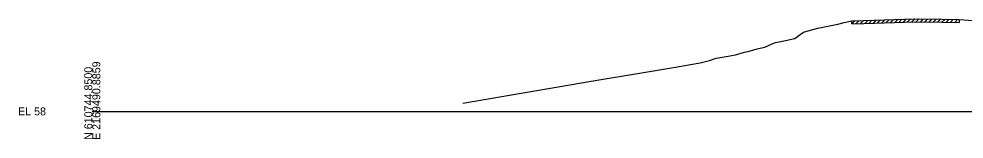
# Model space of a CAD drawing. Extents: x -26 to 6803, y -10 to 19606.
# Drawn here: x 1974.3 to 2305.1, y 8490.3 to 8532.3 of the extents above; entities that cross this region are included whole.
import ezdxf

# ---------------------------------------------------------------- set-up
doc = ezdxf.new("R2010")
doc.units = 0
for name, color, linetype in [('RD_GPK_XS_Cell', 7, 'Continuous'), ('RD_XS_ExGround', 7, 'Continuous'), ('RD_XS_ExPaveRet', 7, 'Continuous')]:
    doc.layers.add(name, color=color, linetype=linetype)

msp = doc.modelspace()

# ---------------------------------------------------------------- linework, layer by layer
at = {"layer": 'RD_GPK_XS_Cell'}
msp.add_line((2000, 8500), (2400, 8500), dxfattribs=at)
at = {"layer": 'RD_XS_ExGround'}
msp.add_lwpolyline([(2129.68, 8502.91), (2175.98, 8510.84), (2192.19, 8513.53), (2204.05, 8515.47), (2209.37, 8516.39), (2212.68, 8516.97), (2216.04, 8517.77), (2218.36, 8518.66), (2222.55, 8519.3), (2225.14, 8519.75), (2228.2, 8520.7), (2229.37, 8520.91), (2231.51, 8521.51), (2232.69, 8521.85), (2235.4, 8522.5), (2237.97, 8523.6), (2239.11, 8524.12), (2240.93, 8524.49), (2245.91, 8525.47), (2247.69, 8526.91), (2248.88, 8527.65), (2249.27, 8527.79), (2253.91, 8529.06), (2260.89, 8530.46), (2263.14, 8531.1), (2265.83, 8531.65), (2270.04, 8531.78), (2287.81, 8532.34), (2297.43, 8532.21), (2303.39, 8532.12), (2309.93, 8531.68)], dxfattribs=at)
at = {"layer": 'RD_XS_ExPaveRet'}
for p, q in [((2265.83, 8530.65), (2266.86, 8531.68)), ((2265.83, 8530.65), (2265.83, 8531.65)), ((2267.33, 8530.7), (2268.36, 8531.73)), ((2268.83, 8530.74), (2269.86, 8531.78)), ((2270.04, 8530.78), (2287.81, 8531.34)), ((2270.33, 8530.79), (2271.36, 8531.82)), ((2271.83, 8530.84), (2272.86, 8531.87)), ((2273.33, 8530.89), (2274.36, 8531.92)), ((2274.83, 8530.93), (2275.86, 8531.97)), ((2276.33, 8530.98), (2277.36, 8532.01)), ((2277.83, 8531.03), (2278.86, 8532.06)), ((2279.33, 8531.07), (2280.36, 8532.11)), ((2280.83, 8531.12), (2281.86, 8532.15)), ((2282.33, 8531.17), (2283.36, 8532.2)), ((2283.83, 8531.21), (2284.86, 8532.25)), ((2285.33, 8531.26), (2286.36, 8532.29)), ((2286.83, 8531.31), (2287.86, 8532.34)), ((2287.81, 8531.34), (2297.43, 8531.21)), ((2288.33, 8531.33), (2289.32, 8532.32)), ((2289.83, 8531.31), (2290.82, 8532.3)), ((2291.33, 8531.29), (2292.32, 8532.28)), ((2292.83, 8531.27), (2293.82, 8532.26)), ((2294.33, 8531.25), (2295.32, 8532.24)), ((2295.83, 8531.23), (2296.82, 8532.22)), ((2297.33, 8531.21), (2298.31, 8532.19)), ((2298.83, 8531.19), (2299.81, 8532.17)), ((2300.33, 8531.16), (2301.31, 8532.15)), ((2301.83, 8531.14), (2302.81, 8532.12)), ((2303.39, 8532.12), (2303.39, 8531.12)), ((2265.83, 8530.65), (2270.04, 8530.78)), ((2297.43, 8531.21), (2303.39, 8531.12)), ((2303.39, 8531.12), (2303.39, 8531.12))]:
    msp.add_line(p, q, dxfattribs=at)

# ---------------------------------------------------------------- texts
at = {"layer": 'RD_GPK_XS_Cell'}
for s, p in [('N 610744.8500', (2000, 8490)), ('E 2169490.8859', (2002.8, 8490))]:
    msp.add_text(s, height=2.8, rotation=90, dxfattribs=at).set_placement(p)
msp.add_text('EL 58', height=2.8, dxfattribs=at).set_placement((1974, 8498.6))

doc.saveas('drawing.dxf')
